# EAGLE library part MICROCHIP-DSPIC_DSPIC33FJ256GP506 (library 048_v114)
dsPIC33 General DSC with CAN and CoDec ports
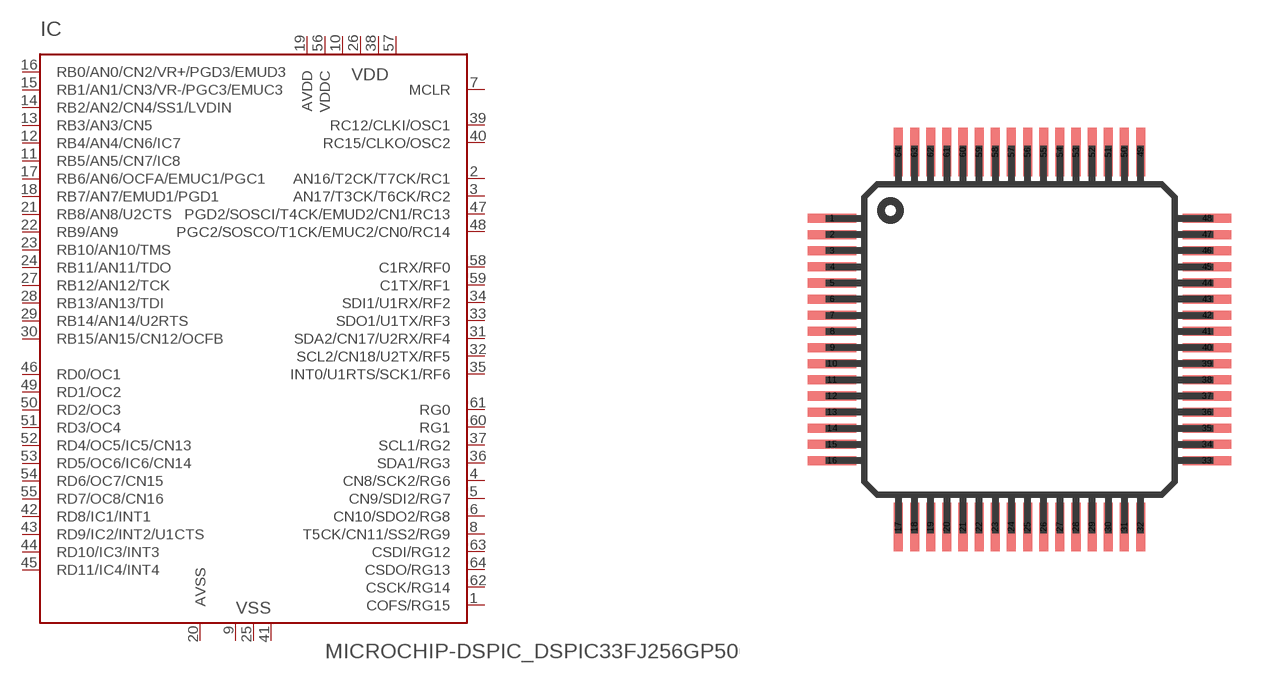
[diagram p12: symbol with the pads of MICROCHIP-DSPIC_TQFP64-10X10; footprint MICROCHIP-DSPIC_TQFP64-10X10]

Designator prefix IC

## MICROCHIP-DSPIC_DSPIC33FJ256GP506/PT  [MICROCHIP-DSPIC_TQFP64-10X10]
1  COFS/RG15
2  AN16/T2CK/T7CK/RC1
3  AN17/T3CK/T6CK/RC2
4  CN8/SCK2/RG6
5  CN9/SDI2/RG7
6  CN10/SDO2/RG8
7  MCLR  in
8  T5CK/CN11/SS2/RG9
9  VSS  pwr
10  VDD  pwr
11  RB5/AN5/CN7/IC8
12  RB4/AN4/CN6/IC7
13  RB3/AN3/CN5
14  RB2/AN2/CN4/SS1/LVDIN
15  RB1/AN1/CN3/VR-/PGC3/EMUC3
16  RB0/AN0/CN2/VR+/PGD3/EMUD3
17  RB6/AN6/OCFA/EMUC1/PGC1
18  RB7/AN7/EMUD1/PGD1
19  AVDD  pwr
20  AVSS  pwr
21  RB8/AN8/U2CTS
22  RB9/AN9
23  RB10/AN10/TMS
24  RB11/AN11/TDO
25  VSS  pwr
26  VDD  pwr
27  RB12/AN12/TCK
28  RB13/AN13/TDI
29  RB14/AN14/U2RTS
30  RB15/AN15/CN12/OCFB
31  SDA2/CN17/U2RX/RF4
32  SCL2/CN18/U2TX/RF5
33  SDO1/U1TX/RF3
34  SDI1/U1RX/RF2
35  INT0/U1RTS/SCK1/RF6
36  SDA1/RG3
37  SCL1/RG2
38  VDD  pwr
39  RC12/CLKI/OSC1
40  RC15/CLKO/OSC2
41  VSS  pwr
42  RD8/IC1/INT1
43  RD9/IC2/INT2/U1CTS
44  RD10/IC3/INT3
45  RD11/IC4/INT4
46  RD0/OC1
47  PGD2/SOSCI/T4CK/EMUD2/CN1/RC13
48  PGC2/SOSCO/T1CK/EMUC2/CN0/RC14
49  RD1/OC2
50  RD2/OC3
51  RD3/OC4
52  RD4/OC5/IC5/CN13
53  RD5/OC6/IC6/CN14
54  RD6/OC7/CN15
55  RD7/OC8/CN16
56  VDDC  pwr
57  VDD  pwr
58  C1RX/RF0
59  C1TX/RF1
60  RG1
61  RG0
62  CSCK/RG14
63  CSDI/RG12
64  CSDO/RG13

## Footprint MICROCHIP-DSPIC_TQFP64-10X10 (pad centres in mm)
Thin Quad Flat Pack package type TQ
smd 1.5 x 0.28: 1 -5.8,3.75; 2 -5.8,3.25; 3 -5.8,2.75; 4 -5.8,2.25; 5 -5.8,1.75; 6 -5.8,1.25; 7 -5.8,0.75; 8 -5.8,0.25; 9 -5.8,-0.25; 10 -5.8,-0.75; 11 -5.8,-1.25; 12 -5.8,-1.75; 13 -5.8,-2.25; 14 -5.8,-2.75; 15 -5.8,-3.25; 16 -5.8,-3.75; 33 5.8,-3.75; 34 5.8,-3.25; 35 5.8,-2.75; 36 5.8,-2.25; 37 5.8,-1.75; 38 5.8,-1.25; 39 5.8,-0.75; 40 5.8,-0.25; 41 5.8,0.25; 42 5.8,0.75; 43 5.8,1.25; 44 5.8,1.75; 45 5.8,2.25; 46 5.8,2.75; 47 5.8,3.25; 48 5.8,3.75
smd 0.28 x 1.5: 17 -3.75,-5.8; 18 -3.25,-5.8; 19 -2.75,-5.8; 20 -2.25,-5.8; 21 -1.75,-5.8; 22 -1.25,-5.8; 23 -0.75,-5.8; 24 -0.25,-5.8; 25 0.25,-5.8; 26 0.75,-5.8; 27 1.25,-5.8; 28 1.75,-5.8; 29 2.25,-5.8; 30 2.75,-5.8; 31 3.25,-5.8; 32 3.75,-5.8; 49 3.75,5.8; 50 3.25,5.8; 51 2.75,5.8; 52 2.25,5.8; 53 1.75,5.8; 54 1.25,5.8; 55 0.75,5.8; 56 0.25,5.8; 57 -0.25,5.8; 58 -0.75,5.8; 59 -1.25,5.8; 60 -1.75,5.8; 61 -2.25,5.8; 62 -2.75,5.8; 63 -3.25,5.8; 64 -3.75,5.8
